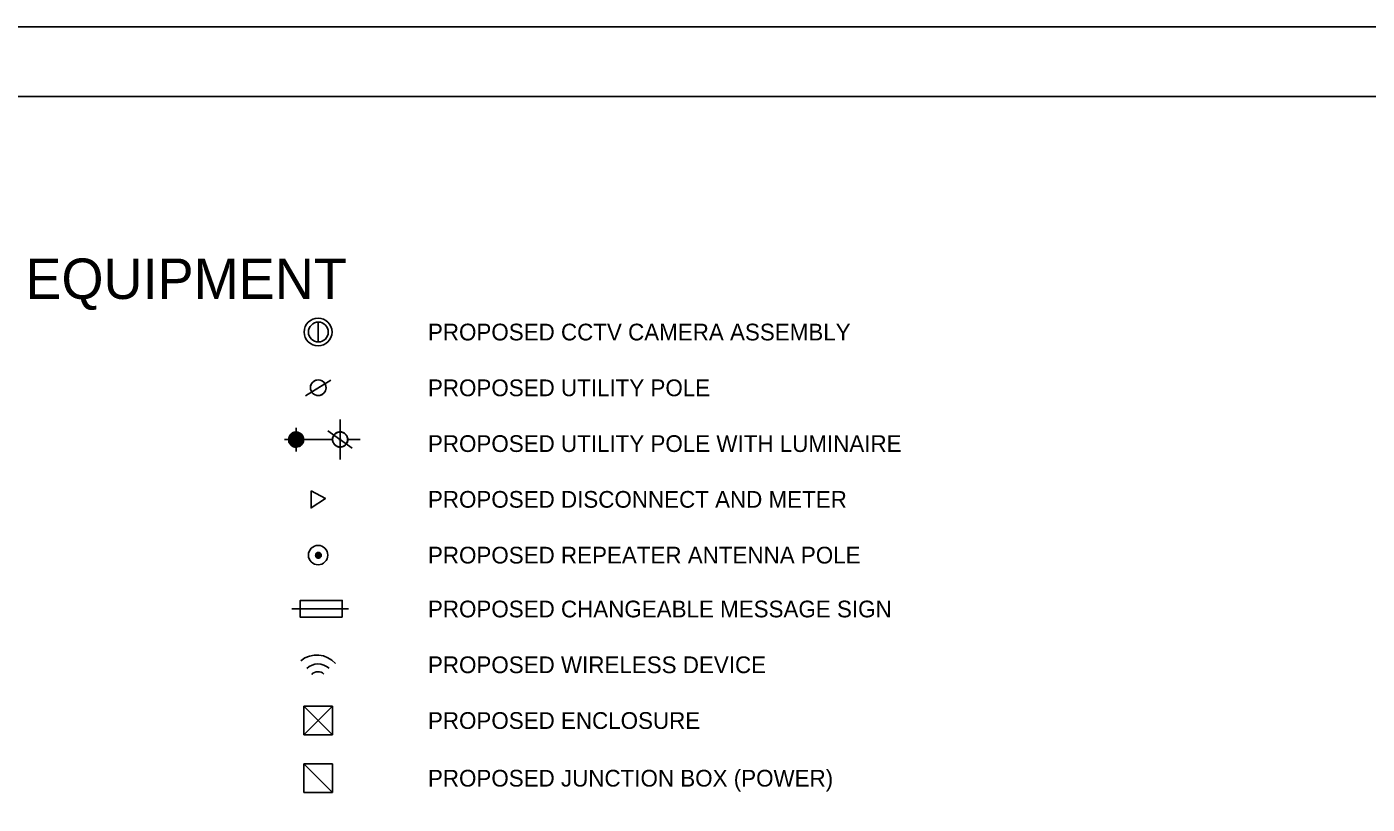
# Model space of a CAD drawing. Extents: x 1299104.8 to 1299141.6, y 239639.8 to 239661.8.
# Drawn here: x 1299111.89 to 1299121.51, y 239656.22 to 239661.79 of the extents above; entities that cross this region are included whole.
import ezdxf

# ---------------------------------------------------------------- set-up
doc = ezdxf.new("R2010")
doc.units = 0
for name, color, linetype in [('DIM TXT', 7, 'Continuous'), ('GS_noplot_1', 7, 'Continuous'), ('Level 1', 7, 'Continuous'), ('PDF3_Geometry', 7, 'Continuous'), ('PDF_ITS-POWR-OVHD', 7, 'Continuous'), ('PDF_ITS-POWR-POLE', 7, 'Continuous'), ('PDF_LEGEND', 7, 'Continuous'), ('PTEXT', 7, 'Continuous')]:
    doc.layers.add(name, color=color, linetype=linetype)

msp = doc.modelspace()

# ---------------------------------------------------------------- linework, layer by layer
at = {"layer": 'GS_noplot_1'}
msp.add_lwpolyline([(1299104.8019, 239661.7913), (1299138.8019, 239661.7913), (1299138.8019, 239639.7913), (1299104.8019, 239639.7913)], close=True, dxfattribs=at)
at = {"layer": 'Level 1'}
msp.add_lwpolyline([(1299138.3019, 239640.2913), (1299106.3019, 239640.2913), (1299106.3019, 239661.2913), (1299138.3019, 239661.2913)], close=True, dxfattribs=at)
at = {"layer": 'PDF3_Geometry'}
for points in [[(1299113.8262, 239658.8843), (1299113.8248, 239658.915)], [(1299114.1401, 239658.8926), (1299114.1401, 239658.975)], [(1299114.1415, 239658.7475), (1299114.1415, 239658.9163)], [(1299113.7717, 239658.8312), (1299113.741, 239658.8312)], [(1299114.0871, 239658.8312), (1299113.8792, 239658.8312)], [(1299114.0787, 239658.8312), (1299113.9964, 239658.8312)], [(1299114.228, 239658.7684), (1299114.0536, 239658.894)], [(1299114.2029, 239658.8312), (1299114.2838, 239658.8312)], [(1299113.8262, 239658.7461), (1299113.8262, 239658.7768)], [(1299114.1415, 239658.7698), (1299114.1415, 239658.6875)]]:
    msp.add_lwpolyline(points, dxfattribs=at)
for centre, radius, start, end in [((1299113.8257, 239658.8312), 0.0539, 135.66759, 179.99972), ((1299113.8262, 239658.8303), 0.0539, 45.66759, 89.99972), ((1299113.8253, 239658.8312), 0.0539, 0.00028, 44.33241), ((1299114.1369, 239658.8316), 0.0498, 131.60231, 180.47271), ((1299114.1445, 239658.835), 0.0587, 191.96926, 233.26922), ((1299114.1411, 239658.8358), 0.0498, 89.52729, 138.39769), ((1299114.1419, 239658.8358), 0.0498, 41.60231, 90.47271), ((1299113.8262, 239658.8307), 0.0539, 270.00028, 314.33241), ((1299114.1415, 239658.8321), 0.0539, 225.66759, 314.33241)]:
    msp.add_arc(centre, radius, start, end, dxfattribs=at)
for points in [[(1299113.7717, 239658.8312), (1299113.7717, 239658.8159), (1299113.7773, 239658.8033), (1299113.7871, 239658.7922)], [(1299113.8262, 239658.8843), (1299113.8108, 239658.8843), (1299113.7969, 239658.8787), (1299113.7871, 239658.8689)], [(1299113.8638, 239658.7922), (1299113.8736, 239658.8033), (1299113.8792, 239658.8173), (1299113.8792, 239658.8312)], [(1299114.0885, 239658.8452), (1299114.0857, 239658.8312), (1299114.0871, 239658.8173), (1299114.0941, 239658.8047)], [(1299114.0968, 239658.8633), (1299114.0885, 239658.8508), (1299114.0857, 239658.8368), (1299114.0871, 239658.8229)], [(1299114.0871, 239658.8312), (1299114.0871, 239658.8173), (1299114.0941, 239658.8033), (1299114.1038, 239658.7936)], [(1299114.1136, 239658.8773), (1299114.101, 239658.8703), (1299114.0927, 239658.8591), (1299114.0885, 239658.8452)], [(1299114.1317, 239658.8843), (1299114.1178, 239658.8829), (1299114.1052, 239658.8745), (1299114.0968, 239658.8633)], [(1299114.1541, 239658.8829), (1299114.1401, 239658.887), (1299114.1261, 239658.8843), (1299114.1136, 239658.8773)], [(1299114.1722, 239658.8745), (1299114.161, 239658.8829), (1299114.1457, 239658.887), (1299114.1317, 239658.8843)], [(1299114.1401, 239658.8354), (1299114.1387, 239658.8354), (1299114.1359, 239658.834), (1299114.1359, 239658.8312)], [(1299114.1359, 239658.8312), (1299114.1359, 239658.8284), (1299114.1387, 239658.827), (1299114.1401, 239658.827)], [(1299114.1443, 239658.8312), (1299114.1443, 239658.834), (1299114.1429, 239658.8354), (1299114.1401, 239658.8354)], [(1299114.1401, 239658.827), (1299114.1429, 239658.827), (1299114.1443, 239658.8284), (1299114.1443, 239658.8312)], [(1299114.1875, 239658.8577), (1299114.1792, 239658.8703), (1299114.168, 239658.8801), (1299114.1541, 239658.8829)], [(1299114.168, 239658.7852), (1299114.1792, 239658.7922), (1299114.1889, 239658.8047), (1299114.1917, 239658.8173)], [(1299114.1931, 239658.8396), (1299114.1917, 239658.8536), (1299114.1834, 239658.8661), (1299114.1722, 239658.8745)], [(1299114.1959, 239658.8312), (1299114.1945, 239658.8452), (1299114.1889, 239658.8591), (1299114.1792, 239658.8689)], [(1299114.1792, 239658.7936), (1299114.1889, 239658.8033), (1299114.1959, 239658.8173), (1299114.1959, 239658.8312)], [(1299114.1848, 239658.8005), (1299114.1931, 239658.8117), (1299114.1959, 239658.8257), (1299114.1931, 239658.8396)], [(1299114.1917, 239658.8173), (1299114.1959, 239658.8312), (1299114.1945, 239658.8466), (1299114.1875, 239658.8577)], [(1299113.7871, 239658.7922), (1299113.7983, 239658.7824), (1299113.8108, 239658.7768), (1299113.8262, 239658.7768)], [(1299114.0941, 239658.8047), (1299114.101, 239658.7922), (1299114.1136, 239658.7838), (1299114.1275, 239658.7796)], [(1299114.1094, 239658.788), (1299114.1206, 239658.7796), (1299114.1345, 239658.7754), (1299114.1499, 239658.7782)], [(1299114.1275, 239658.7796), (1299114.1401, 239658.7768), (1299114.1555, 239658.7782), (1299114.168, 239658.7852)], [(1299114.1499, 239658.7782), (1299114.1638, 239658.781), (1299114.1764, 239658.788), (1299114.1848, 239658.8005)]]:
    msp.add_open_spline(points, degree=2, dxfattribs=at)
at = {"layer": 'PDF_ITS-POWR-OVHD'}
msp.add_lwpolyline([(1299114.0736, 239659.2572), (1299113.8927, 239659.145)], dxfattribs=at)
msp.add_circle((1299113.984, 239659.2028), 0.0561, dxfattribs=at)
at = {"layer": 'PDF_ITS-POWR-POLE'}
msp.add_lwpolyline([(1299113.9329, 239658.4639), (1299113.9329, 239658.34), (1299114.036, 239658.4072)], close=True, dxfattribs=at)
at = {"layer": 'PDF_LEGEND'}
for p, q in [((1299113.772, 239658.8259), (1299113.772, 239658.8362)), ((1299113.7725, 239658.8219), (1299113.7725, 239658.8401)), ((1299113.773, 239658.8192), (1299113.773, 239658.8427)), ((1299113.7735, 239658.8171), (1299113.7735, 239658.8448)), ((1299113.774, 239658.8152), (1299113.774, 239658.8466)), ((1299113.7745, 239658.8136), (1299113.7745, 239658.8482)), ((1299113.775, 239658.8122), (1299113.775, 239658.8496)), ((1299113.7755, 239658.8108), (1299113.7755, 239658.8509)), ((1299113.776, 239658.8096), (1299113.776, 239658.8522)), ((1299113.7765, 239658.8084), (1299113.7765, 239658.8533)), ((1299113.777, 239658.8073), (1299113.777, 239658.8544)), ((1299113.7775, 239658.8063), (1299113.7775, 239658.8554)), ((1299113.778, 239658.8053), (1299113.778, 239658.8564)), ((1299113.7785, 239658.8044), (1299113.7785, 239658.8573)), ((1299113.779, 239658.8035), (1299113.779, 239658.8582)), ((1299113.7795, 239658.8026), (1299113.7795, 239658.8591)), ((1299113.78, 239658.8018), (1299113.78, 239658.8599)), ((1299113.7805, 239658.801), (1299113.7805, 239658.8606)), ((1299113.781, 239658.8002), (1299113.781, 239658.8614)), ((1299113.7815, 239658.7994), (1299113.7815, 239658.8621)), ((1299113.782, 239658.7987), (1299113.782, 239658.8628)), ((1299113.7825, 239658.798), (1299113.7825, 239658.8635)), ((1299113.783, 239658.7973), (1299113.783, 239658.8642)), ((1299113.7835, 239658.7966), (1299113.7835, 239658.8648)), ((1299113.784, 239658.796), (1299113.784, 239658.8654)), ((1299113.7845, 239658.7953), (1299113.7845, 239658.866)), ((1299113.785, 239658.7947), (1299113.785, 239658.8666)), ((1299113.7855, 239658.7941), (1299113.7855, 239658.8672)), ((1299113.786, 239658.7935), (1299113.786, 239658.8677)), ((1299113.7865, 239658.7929), (1299113.7865, 239658.8683)), ((1299113.787, 239658.7923), (1299113.787, 239658.8688)), ((1299113.7875, 239658.7918), (1299113.7875, 239658.8693)), ((1299113.788, 239658.7914), (1299113.788, 239658.8698)), ((1299113.7885, 239658.791), (1299113.7885, 239658.8702)), ((1299113.789, 239658.7906), (1299113.789, 239658.8707)), ((1299113.7895, 239658.7902), (1299113.7895, 239658.8711)), ((1299113.79, 239658.7898), (1299113.79, 239658.8716)), ((1299113.7905, 239658.7894), (1299113.7905, 239658.872)), ((1299113.791, 239658.789), (1299113.791, 239658.8724)), ((1299113.7915, 239658.7886), (1299113.7915, 239658.8728)), ((1299113.792, 239658.7882), (1299113.792, 239658.8732)), ((1299113.7925, 239658.7879), (1299113.7925, 239658.8736)), ((1299113.793, 239658.7875), (1299113.793, 239658.8739)), ((1299113.7935, 239658.7872), (1299113.7935, 239658.8743)), ((1299113.794, 239658.7868), (1299113.794, 239658.8746)), ((1299113.7945, 239658.7865), (1299113.7945, 239658.875)), ((1299113.795, 239658.7861), (1299113.795, 239658.8753)), ((1299113.7955, 239658.7858), (1299113.7955, 239658.8756)), ((1299113.796, 239658.7855), (1299113.796, 239658.8759)), ((1299113.7965, 239658.7852), (1299113.7965, 239658.8763)), ((1299113.797, 239658.7849), (1299113.797, 239658.8766)), ((1299113.7975, 239658.7846), (1299113.7975, 239658.8768)), ((1299113.798, 239658.7843), (1299113.798, 239658.8771)), ((1299113.7985, 239658.784), (1299113.7985, 239658.8774)), ((1299113.799, 239658.7837), (1299113.799, 239658.8777)), ((1299113.7995, 239658.7835), (1299113.7995, 239658.8779)), ((1299113.8, 239658.7832), (1299113.8, 239658.8782)), ((1299113.8005, 239658.7829), (1299113.8005, 239658.8784)), ((1299113.801, 239658.7827), (1299113.801, 239658.8787)), ((1299113.8015, 239658.7824), (1299113.8015, 239658.8789)), ((1299113.802, 239658.7822), (1299113.802, 239658.8792)), ((1299113.8025, 239658.782), (1299113.8025, 239658.8794)), ((1299113.803, 239658.7817), (1299113.803, 239658.8796)), ((1299113.8035, 239658.7815), (1299113.8035, 239658.8798)), ((1299113.804, 239658.7813), (1299113.804, 239658.88)), ((1299113.8045, 239658.7811), (1299113.8045, 239658.8802)), ((1299113.805, 239658.7809), (1299113.805, 239658.8804)), ((1299113.8055, 239658.7807), (1299113.8055, 239658.8806)), ((1299113.806, 239658.7805), (1299113.806, 239658.8808)), ((1299113.8065, 239658.7803), (1299113.8065, 239658.881)), ((1299113.807, 239658.7801), (1299113.807, 239658.8811)), ((1299113.8075, 239658.7799), (1299113.8075, 239658.8813)), ((1299113.808, 239658.7797), (1299113.808, 239658.8815)), ((1299113.8085, 239658.7796), (1299113.8085, 239658.8816)), ((1299113.809, 239658.7794), (1299113.809, 239658.8818)), ((1299113.8095, 239658.7793), (1299113.8095, 239658.8819)), ((1299113.81, 239658.7791), (1299113.81, 239658.8821)), ((1299113.8105, 239658.779), (1299113.8105, 239658.8822)), ((1299113.811, 239658.7788), (1299113.811, 239658.8823)), ((1299113.8115, 239658.7787), (1299113.8115, 239658.8825)), ((1299113.812, 239658.7786), (1299113.812, 239658.8826)), ((1299113.8125, 239658.7784), (1299113.8125, 239658.8827)), ((1299113.813, 239658.7783), (1299113.813, 239658.8828)), ((1299113.8135, 239658.7782), (1299113.8135, 239658.8829)), ((1299113.814, 239658.7781), (1299113.814, 239658.883)), ((1299113.8145, 239658.778), (1299113.8145, 239658.8831)), ((1299113.815, 239658.7779), (1299113.815, 239658.8832)), ((1299113.8155, 239658.7778), (1299113.8155, 239658.8833)), ((1299113.816, 239658.7777), (1299113.816, 239658.8834)), ((1299113.8165, 239658.7776), (1299113.8165, 239658.8835)), ((1299113.817, 239658.7775), (1299113.817, 239658.8836)), ((1299113.8175, 239658.7774), (1299113.8175, 239658.8836)), ((1299113.818, 239658.7774), (1299113.818, 239658.8837)), ((1299113.8185, 239658.7773), (1299113.8185, 239658.8838)), ((1299113.819, 239658.7772), (1299113.819, 239658.8838)), ((1299113.8195, 239658.7772), (1299113.8195, 239658.8839)), ((1299113.82, 239658.7771), (1299113.82, 239658.8839)), ((1299113.8205, 239658.7771), (1299113.8205, 239658.884)), ((1299113.821, 239658.777), (1299113.821, 239658.884)), ((1299113.8215, 239658.777), (1299113.8215, 239658.8841)), ((1299113.822, 239658.777), (1299113.822, 239658.8841)), ((1299113.8225, 239658.7769), (1299113.8225, 239658.8841)), ((1299113.823, 239658.7769), (1299113.823, 239658.8842)), ((1299113.8235, 239658.7769), (1299113.8235, 239658.8842)), ((1299113.824, 239658.7769), (1299113.824, 239658.8842)), ((1299113.8245, 239658.7768), (1299113.8245, 239658.8842)), ((1299113.825, 239658.7768), (1299113.825, 239658.8842)), ((1299113.8255, 239658.7768), (1299113.8255, 239658.8843)), ((1299113.826, 239658.7768), (1299113.826, 239658.8843)), ((1299113.8265, 239658.7768), (1299113.8265, 239658.8843)), ((1299113.827, 239658.7768), (1299113.827, 239658.8842)), ((1299113.8275, 239658.7768), (1299113.8275, 239658.8842)), ((1299113.828, 239658.7768), (1299113.828, 239658.8842)), ((1299113.8285, 239658.7769), (1299113.8285, 239658.8842)), ((1299113.829, 239658.7769), (1299113.829, 239658.8842)), ((1299113.8295, 239658.7769), (1299113.8295, 239658.8842)), ((1299113.83, 239658.777), (1299113.83, 239658.8841)), ((1299113.8305, 239658.777), (1299113.8305, 239658.8841)), ((1299113.831, 239658.777), (1299113.831, 239658.884)), ((1299113.8315, 239658.7771), (1299113.8315, 239658.884)), ((1299113.832, 239658.7771), (1299113.832, 239658.8839)), ((1299113.8325, 239658.7772), (1299113.8325, 239658.8839)), ((1299113.833, 239658.7772), (1299113.833, 239658.8838)), ((1299113.8335, 239658.7773), (1299113.8335, 239658.8838)), ((1299113.834, 239658.7774), (1299113.834, 239658.8837)), ((1299113.8345, 239658.7775), (1299113.8345, 239658.8836)), ((1299113.835, 239658.7775), (1299113.835, 239658.8835)), ((1299113.8355, 239658.7776), (1299113.8355, 239658.8834)), ((1299113.836, 239658.7777), (1299113.836, 239658.8834)), ((1299113.8365, 239658.7778), (1299113.8365, 239658.8833)), ((1299113.837, 239658.7779), (1299113.837, 239658.8832)), ((1299113.8375, 239658.778), (1299113.8375, 239658.8831)), ((1299113.838, 239658.7781), (1299113.838, 239658.8829)), ((1299113.8385, 239658.7782), (1299113.8385, 239658.8828)), ((1299113.839, 239658.7784), (1299113.839, 239658.8827)), ((1299113.8395, 239658.7785), (1299113.8395, 239658.8826)), ((1299113.84, 239658.7786), (1299113.84, 239658.8825)), ((1299113.8405, 239658.7788), (1299113.8405, 239658.8823)), ((1299113.841, 239658.7789), (1299113.841, 239658.8822)), ((1299113.8415, 239658.779), (1299113.8415, 239658.882)), ((1299113.842, 239658.7792), (1299113.842, 239658.8819)), ((1299113.8425, 239658.7793), (1299113.8425, 239658.8817)), ((1299113.843, 239658.7795), (1299113.843, 239658.8816)), ((1299113.8435, 239658.7797), (1299113.8435, 239658.8814)), ((1299113.844, 239658.7798), (1299113.844, 239658.8812)), ((1299113.8445, 239658.78), (1299113.8445, 239658.881)), ((1299113.845, 239658.7802), (1299113.845, 239658.8809)), ((1299113.8455, 239658.7804), (1299113.8455, 239658.8807)), ((1299113.846, 239658.7806), (1299113.846, 239658.8805)), ((1299113.8465, 239658.7808), (1299113.8465, 239658.8803)), ((1299113.847, 239658.781), (1299113.847, 239658.8801)), ((1299113.8475, 239658.7812), (1299113.8475, 239658.8799)), ((1299113.848, 239658.7814), (1299113.848, 239658.8796)), ((1299113.8485, 239658.7817), (1299113.8485, 239658.8794)), ((1299113.849, 239658.7819), (1299113.849, 239658.8792)), ((1299113.8495, 239658.7821), (1299113.8495, 239658.879)), ((1299113.85, 239658.7824), (1299113.85, 239658.8787)), ((1299113.8505, 239658.7826), (1299113.8505, 239658.8785)), ((1299113.851, 239658.7829), (1299113.851, 239658.8782)), ((1299113.8515, 239658.7831), (1299113.8515, 239658.8779)), ((1299113.852, 239658.7834), (1299113.852, 239658.8777)), ((1299113.8525, 239658.7837), (1299113.8525, 239658.8774)), ((1299113.853, 239658.784), (1299113.853, 239658.8771)), ((1299113.8535, 239658.7842), (1299113.8535, 239658.8768)), ((1299113.854, 239658.7845), (1299113.854, 239658.8765)), ((1299113.8545, 239658.7849), (1299113.8545, 239658.8762)), ((1299113.855, 239658.7852), (1299113.855, 239658.8759)), ((1299113.8555, 239658.7855), (1299113.8555, 239658.8756)), ((1299113.856, 239658.7858), (1299113.856, 239658.8753)), ((1299113.8565, 239658.7861), (1299113.8565, 239658.8749)), ((1299113.857, 239658.7865), (1299113.857, 239658.8746)), ((1299113.8575, 239658.7868), (1299113.8575, 239658.8742)), ((1299113.858, 239658.7872), (1299113.858, 239658.8739)), ((1299113.8585, 239658.7876), (1299113.8585, 239658.8735)), ((1299113.859, 239658.788), (1299113.859, 239658.8731)), ((1299113.8595, 239658.7883), (1299113.8595, 239658.8727)), ((1299113.86, 239658.7887), (1299113.86, 239658.8723)), ((1299113.8605, 239658.7891), (1299113.8605, 239658.8719)), ((1299113.861, 239658.7896), (1299113.861, 239658.8715)), ((1299113.8615, 239658.79), (1299113.8615, 239658.8711)), ((1299113.862, 239658.7904), (1299113.862, 239658.8706)), ((1299113.8625, 239658.7909), (1299113.8625, 239658.8702)), ((1299113.863, 239658.7913), (1299113.863, 239658.8697)), ((1299113.8635, 239658.7918), (1299113.8635, 239658.8693)), ((1299113.864, 239658.7923), (1299113.864, 239658.8688)), ((1299113.8645, 239658.7929), (1299113.8645, 239658.8682)), ((1299113.865, 239658.7935), (1299113.865, 239658.8677)), ((1299113.8655, 239658.7941), (1299113.8655, 239658.8672)), ((1299113.866, 239658.7947), (1299113.866, 239658.8666)), ((1299113.8665, 239658.7954), (1299113.8665, 239658.866)), ((1299113.867, 239658.796), (1299113.867, 239658.8654)), ((1299113.8675, 239658.7967), (1299113.8675, 239658.8648)), ((1299113.868, 239658.7974), (1299113.868, 239658.8641)), ((1299113.8685, 239658.7981), (1299113.8685, 239658.8635)), ((1299113.869, 239658.7989), (1299113.869, 239658.8628)), ((1299113.8695, 239658.7996), (1299113.8695, 239658.8621)), ((1299113.87, 239658.8004), (1299113.87, 239658.8614)), ((1299113.8705, 239658.8012), (1299113.8705, 239658.8606)), ((1299113.871, 239658.8021), (1299113.871, 239658.8598)), ((1299113.8715, 239658.8029), (1299113.8715, 239658.859)), ((1299113.872, 239658.8038), (1299113.872, 239658.8582)), ((1299113.8725, 239658.8048), (1299113.8725, 239658.8573)), ((1299113.873, 239658.8057), (1299113.873, 239658.8563)), ((1299113.8735, 239658.8068), (1299113.8735, 239658.8554)), ((1299113.874, 239658.8078), (1299113.874, 239658.8543)), ((1299113.8745, 239658.809), (1299113.8745, 239658.8533)), ((1299113.875, 239658.8102), (1299113.875, 239658.8521)), ((1299113.8755, 239658.8114), (1299113.8755, 239658.8509)), ((1299113.876, 239658.8128), (1299113.876, 239658.8495)), ((1299113.8765, 239658.8143), (1299113.8765, 239658.8481)), ((1299113.877, 239658.8159), (1299113.877, 239658.8465)), ((1299113.8775, 239658.8178), (1299113.8775, 239658.8447)), ((1299113.878, 239658.8199), (1299113.878, 239658.8426)), ((1299113.8785, 239658.8226), (1299113.8785, 239658.8399)), ((1299113.879, 239658.8266), (1299113.879, 239658.8359))]:
    msp.add_line(p, q, dxfattribs=at)
for points in [[(1299113.984, 239659.5324), (1299113.984, 239659.6731)], [(1299113.7945, 239657.6171), (1299114.2015, 239657.6171)], [(1299114.0853, 239656.9177), (1299113.881, 239656.7134)], [(1299113.881, 239656.9177), (1299114.0853, 239656.7134)]]:
    msp.add_lwpolyline(points, dxfattribs=at)
for points in [[(1299113.9655, 239658.0044), (1299114.0041, 239658.0011), (1299113.9639, 239658.0011)], [(1299114.0041, 239658.0011), (1299113.9639, 239658.0011), (1299114.0041, 239657.9977)], [(1299113.9639, 239658.0011), (1299114.0041, 239657.9977), (1299113.9655, 239657.9977)], [(1299113.9672, 239658.0111), (1299114.0041, 239658.0078), (1299113.9655, 239658.0078)], [(1299114.0041, 239658.0078), (1299113.9655, 239658.0078), (1299114.0041, 239658.0044)], [(1299113.9655, 239658.0078), (1299114.0041, 239658.0044), (1299113.9655, 239658.0044)], [(1299114.0041, 239658.0044), (1299113.9655, 239658.0044), (1299114.0041, 239658.0011)], [(1299114.0041, 239657.9977), (1299113.9655, 239657.9977), (1299114.0041, 239657.9927)], [(1299113.9655, 239657.9977), (1299114.0041, 239657.9927), (1299113.9655, 239657.9927)], [(1299114.0041, 239657.9927), (1299113.9655, 239657.9927), (1299114.0024, 239657.9894)], [(1299113.9655, 239657.9927), (1299114.0024, 239657.9894), (1299113.9672, 239657.9894)], [(1299113.9706, 239658.0145), (1299114.0024, 239658.0111), (1299113.9672, 239658.0111)], [(1299114.0024, 239658.0111), (1299113.9672, 239658.0111), (1299114.0041, 239658.0078)], [(1299114.0024, 239657.9894), (1299113.9672, 239657.9894), (1299113.999, 239657.9877)], [(1299113.9672, 239657.9894), (1299113.999, 239657.9877), (1299113.9706, 239657.9877)], [(1299113.9722, 239658.0162), (1299113.999, 239658.0145), (1299113.9706, 239658.0145)], [(1299113.999, 239658.0145), (1299113.9706, 239658.0145), (1299114.0024, 239658.0111)], [(1299113.999, 239657.9877), (1299113.9706, 239657.9877), (1299113.9974, 239657.9844)], [(1299113.9706, 239657.9877), (1299113.9974, 239657.9844), (1299113.9722, 239657.9844)], [(1299113.9756, 239658.0195), (1299113.9974, 239658.0162), (1299113.9722, 239658.0162)], [(1299113.9974, 239658.0162), (1299113.9722, 239658.0162), (1299113.999, 239658.0145)], [(1299113.9974, 239657.9844), (1299113.9722, 239657.9844), (1299113.994, 239657.9827)], [(1299113.9722, 239657.9844), (1299113.994, 239657.9827), (1299113.9756, 239657.9827)], [(1299113.9789, 239658.0195), (1299113.994, 239658.0195), (1299113.9756, 239658.0195)], [(1299113.994, 239658.0195), (1299113.9756, 239658.0195), (1299113.9974, 239658.0162)], [(1299113.994, 239657.9827), (1299113.9756, 239657.9827), (1299113.9907, 239657.981)], [(1299113.9756, 239657.9827), (1299113.9907, 239657.981), (1299113.9789, 239657.981)], [(1299113.9823, 239658.0212), (1299113.9907, 239658.0195), (1299113.9789, 239658.0195)], [(1299113.9907, 239658.0195), (1299113.9789, 239658.0195), (1299113.994, 239658.0195)], [(1299113.9907, 239657.981), (1299113.9789, 239657.981), (1299113.9856, 239657.981)], [(1299113.9789, 239657.981), (1299113.9856, 239657.981), (1299113.9823, 239657.981)], [(1299113.9856, 239658.0212), (1299113.9823, 239658.0212), (1299113.9907, 239658.0195)], [(1299114.1563, 239657.5568), (1299113.8548, 239657.5568), (1299113.8548, 239657.6774), (1299114.1563, 239657.6774)], [(1299114.0049, 239656.9177), (1299114.0853, 239656.9177), (1299114.0853, 239656.7938), (1299114.0853, 239656.7134), (1299114.0066, 239656.7134), (1299113.881, 239656.7134), (1299113.881, 239656.8373), (1299113.881, 239656.9177)], [(1299113.881, 239656.5041), (1299114.0853, 239656.5041), (1299114.0853, 239656.5041)], [(1299114.0853, 239656.2998), (1299113.881, 239656.2998), (1299113.881, 239656.5041)], [(1299113.881, 239656.5041), (1299114.0853, 239656.5041), (1299114.0853, 239656.2998)], [(1299114.0853, 239656.2998), (1299114.0853, 239656.2998), (1299113.881, 239656.2998)]]:
    msp.add_lwpolyline(points, close=True, dxfattribs=at)
for centre, radius in [((1299113.9831, 239659.6019), 0.0996), ((1299113.9848, 239659.6019), 0.0712), ((1299113.9831, 239658.0019), 0.0695), ((1299113.9848, 239658.0019), 0.0193)]:
    msp.add_circle(centre, radius, dxfattribs=at)
for centre, radius, start, end in [((1299113.9724, 239657.105), 0.18, 41.24816, 129.21021), ((1299113.9824, 239657.1017), 0.1197, 48.00476, 132.61597), ((1299113.9824, 239657.105), 0.0611, 46.27993, 137.818)]:
    msp.add_arc(centre, radius, start, end, dxfattribs=at)
at = {"layer": 'PTEXT'}
for p, q in [((1299113.9368, 239659.1724), (1299114.0321, 239659.2315)), ((1299114.0321, 239659.2315), (1299113.9368, 239659.1724))]:
    msp.add_line(p, q, dxfattribs=at)
msp.add_lwpolyline([(1299113.9329, 239658.4639), (1299113.9329, 239658.34), (1299114.036, 239658.4072), (1299113.9329, 239658.4639)], dxfattribs=at)
for start, end in [(30.81163, 212.81685), (212.81685, 30.81163)]:
    msp.add_arc((1299113.984, 239659.2028), 0.0561, start, end, dxfattribs=at)

# ---------------------------------------------------------------- texts
at = {"layer": 'DIM TXT'}
for s, height, p in [('EQUIPMENT', 0.29, (1299111.8835, 239659.8393)), ('PROPOSED CCTV CAMERA ASSEMBLY', 0.12, (1299114.7708, 239659.5419)), ('PROPOSED UTILITY POLE', 0.12, (1299114.7708, 239659.1419)), ('PROPOSED UTILITY POLE WITH LUMINAIRE', 0.12, (1299114.7708, 239658.7419)), ('PROPOSED DISCONNECT AND METER', 0.12, (1299114.7708, 239658.3419)), ('PROPOSED REPEATER ANTENNA POLE', 0.12, (1299114.7708, 239657.9419)), ('PROPOSED CHANGEABLE MESSAGE SIGN', 0.12, (1299114.7708, 239657.5555)), ('PROPOSED WIRELESS DEVICE', 0.12, (1299114.7708, 239657.1555)), ('PROPOSED ENCLOSURE', 0.12, (1299114.7708, 239656.7555)), ('PROPOSED JUNCTION BOX (POWER)', 0.12, (1299114.7708, 239656.3419))]:
    msp.add_text(s, height=height, dxfattribs=at).set_placement(p)

doc.saveas('drawing.dxf')
